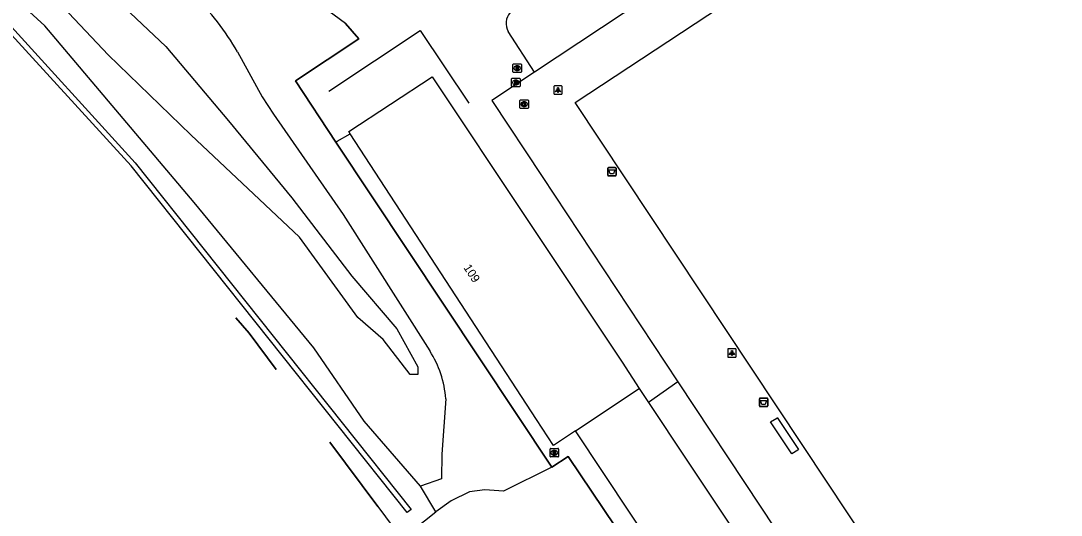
# Model space of a CAD drawing. Extents: x 155640 to 156810, y 382822 to 384046.
# Drawn here: x 156401.1 to 156523.6, y 382930.5 to 382988.7 of the extents above; entities that cross this region are included whole.
import ezdxf

# ---------------------------------------------------------------- set-up
doc = ezdxf.new("R2010")
doc.units = 0
for name, color, linetype in [('IMGEO_Afvalbak', 7, 'Continuous'), ('IMGEO_Groenvoorziening', 7, 'Continuous'), ('IMGEO_Hek', 7, 'Continuous'), ('IMGEO_Kolk', 7, 'Continuous'), ('IMGEO_Lichtpunt', 7, 'Continuous'), ('IMGEO_Pand', 7, 'Continuous'), ('IMGEO_Pand_nummerreeks', 7, 'Continuous'), ('IMGEO_Rioolput', 7, 'Continuous'), ('IMGEO_Voetpad_gesloten', 7, 'Continuous'), ('IMGEO_Voetpad_open', 7, 'Continuous')]:
    doc.layers.add(name, color=color, linetype=linetype)

msp = doc.modelspace()

# ---------------------------------------------------------------- linework, layer by layer
at = {"layer": 'IMGEO_Afvalbak'}
for p, q in [((156470.21, 382970.51), (156470.21, 382971.31)), ((156470.21, 382971.31), (156470.21, 382970.51)), ((156470.31, 382971.41), (156471.09, 382971.41)), ((156471.09, 382971.41), (156470.31, 382971.41)), ((156471.09, 382970.41), (156470.31, 382970.41)), ((156470.31, 382970.41), (156471.09, 382970.41)), ((156471.19, 382971.31), (156471.19, 382970.51)), ((156471.19, 382970.51), (156471.19, 382971.31)), ((156488.06, 382943.37), (156488.06, 382944.17)), ((156488.06, 382944.17), (156488.06, 382943.37)), ((156488.16, 382944.27), (156488.95, 382944.27)), ((156488.95, 382944.27), (156488.16, 382944.27)), ((156489.05, 382944.17), (156489.05, 382943.37)), ((156489.05, 382943.37), (156489.05, 382944.17)), ((156488.95, 382943.27), (156488.16, 382943.27)), ((156488.16, 382943.27), (156488.95, 382943.27))]:
    msp.add_line(p, q, dxfattribs=at)
for points in [[(156470.35, 382971.13), (156471.05, 382971.13), (156470.9, 382970.65), (156470.5, 382970.65), (156470.35, 382971.13)], [(156488.2, 382943.99), (156488.91, 382943.99), (156488.76, 382943.51), (156488.35, 382943.51), (156488.2, 382943.99)]]:
    msp.add_lwpolyline(points, dxfattribs=at)
for centre, start, end in [((156470.31, 382971.31), 90, 180), ((156470.31, 382971.31), 90, 180), ((156470.31, 382970.51), 180, 270), ((156470.31, 382970.51), 180, 270), ((156471.09, 382971.31), 0, 90), ((156471.09, 382971.31), 360, 90), ((156471.09, 382970.51), 270, 0), ((156471.09, 382970.51), 270, 0), ((156488.16, 382944.17), 90, 180), ((156488.16, 382944.17), 90, 180), ((156488.16, 382943.37), 180, 270), ((156488.16, 382943.37), 180, 270), ((156488.95, 382944.17), 0, 90), ((156488.95, 382944.17), 360, 90), ((156488.95, 382943.37), 270, 0), ((156488.95, 382943.37), 270, 0)]:
    msp.add_arc(centre, 0.1, start, end, dxfattribs=at)
at = {"layer": 'IMGEO_Groenvoorziening'}
for points in [[(156359.53, 383023.09), (156398.38, 382989.67), (156414.55, 382971.96), (156447.07, 382931.18), (156446.59, 382930.82), (156414.08, 382971.59), (156397.9, 382989.3), (156359.06, 383022.72), (156319.51, 383051.96), (156317.77, 383054.79), (156251.71, 383103.22), (156251.81, 383103.29), (156252.18, 383103.58), (156318.24, 383055.16), (156319.98, 383052.32), (156359.53, 383023.09)], [(156448.16, 382933.9), (156441.51, 382941.55), (156435.6, 382950.17), (156421.5, 382967.29), (156403.91, 382988.08), (156379.55, 383010.3), (156363.98, 383022.66), (156336.14, 383043.58), (156313.79, 383060.73), (156294.23, 383074.54), (156264.43, 383096.48), (156255.05, 383103.49)], [(156387.91, 383013.08), (156402.17, 383000.77), (156418.19, 382985.62), (156425.56, 382976.88), (156433.01, 382967.82), (156440.09, 382958.61), (156445.36, 382952.4), (156447.86, 382947.96), (156447.86, 382947.03)], [(156447.86, 382947.03), (156446.93, 382947.03), (156443.76, 382951.17), (156440.78, 382953.74), (156433.92, 382963.21), (156421.12, 382975.25), (156411.4, 382984.65), (156398.04, 382998.76)], [(156426.61, 382985.01), (156429.53, 382979.73), (156430.86, 382977.69), (156439.05, 382965.88), (156449.27, 382949.82)], [(156426.42, 382953.7), (156427.98, 382951.89), (156431.15, 382947.63)], [(156451.15, 382944.19), (156450.67, 382937.67), (156450.62, 382934.76), (156448.16, 382933.9)], [(156437.49, 382939.08), (156443.13, 382931.5), (156445.96, 382927.71), (156449.96, 382930.89)], [(156463.61, 382936.15), (156457.95, 382933.32), (156455.75, 382933.47), (156453.93, 382933.22), (156451.77, 382932.2), (156449.96, 382930.89)], [(156449.96, 382930.89), (156448.16, 382933.9)]]:
    msp.add_lwpolyline(points, dxfattribs=at)
for centre, radius, start, end in [((156398.25, 382968.49), 32.83, 30.2247, 45.0445), ((156438.83, 382943.19), 12.36, 4.6367, 32.4104)]:
    msp.add_arc(centre, radius, start, end, dxfattribs=at)
at = {"layer": 'IMGEO_Hek'}
for points in [[(156439.33, 382988.35), (156440.92, 382986.52), (156433.44, 382981.59), (156438.21, 382974.39)], [(156437.38, 382980.39), (156448.13, 382987.51), (156453.85, 382978.96)], [(156438.36, 382974.48), (156439.88, 382975.38)], [(156438.21, 382974.39), (156438.36, 382974.48)], [(156438.21, 382974.39), (156463.61, 382936.15), (156465.54, 382937.4), (156476.61, 382920.96)], [(156431.15, 382947.63), (156427.98, 382951.89), (156426.42, 382953.7)], [(156443.13, 382931.5), (156437.49, 382939.08)]]:
    msp.add_lwpolyline(points, dxfattribs=at)
at = {"layer": 'IMGEO_Kolk'}
for p, q in [((156459.86, 382978.43), (156459.86, 382979.28)), ((156459.94, 382979.36), (156460.79, 382979.36)), ((156460.35, 382979.13), (156460.37, 382979.13)), ((156460.86, 382979.28), (156460.86, 382978.43)), ((156460.79, 382978.35), (156459.94, 382978.35)), ((156460.37, 382978.58), (156460.35, 382978.58))]:
    msp.add_line(p, q, dxfattribs=at)
for points in [[(156459.86, 382978.43), (156459.86, 382979.28)], [(156459.94, 382979.36), (156460.79, 382979.36)], [(156460.18, 382979.05), (156460.31, 382979.05), (156460.31, 382978.9), (156460.43, 382979.05), (156460.6, 382979.05), (156460.45, 382978.9), (156460.61, 382978.65), (156460.45, 382978.65), (156460.37, 382978.82), (156460.31, 382978.75), (156460.31, 382978.65), (156460.18, 382978.65), (156460.18, 382979.05)], [(156460.86, 382979.28), (156460.86, 382978.43)], [(156460.79, 382978.35), (156459.94, 382978.35)]]:
    msp.add_lwpolyline(points, dxfattribs=at)
for centre, start, end in [((156459.94, 382979.28), 91.552, 178.448), ((156459.94, 382979.28), 91.552, 178.448), ((156460.79, 382979.28), 1.552, 88.448), ((156460.79, 382979.28), 1.552, 88.448), ((156459.94, 382978.43), 181.552, 268.448), ((156459.94, 382978.43), 181.552, 268.448), ((156460.79, 382978.43), 271.552, 358.448), ((156460.79, 382978.43), 271.552, 358.448)]:
    msp.add_arc(centre, 0.0765, start, end, dxfattribs=at)
for centre, major_axis, ratio, start_param, end_param in [((156460.35, 382978.85), (-0.387, 0.002), 0.722429, 4.712389, 7.853982), ((156460.37, 382978.85), (-0.39, 0.002), 0.717154, 1.570796, 4.712389)]:
    msp.add_ellipse(centre, major_axis=major_axis, ratio=ratio, start_param=start_param, end_param=end_param, dxfattribs=at)
at = {"layer": 'IMGEO_Lichtpunt'}
for p, q in [((156463.85, 382980.92), (156463.85, 382980.11)), ((156463.85, 382980.92), (156463.85, 382980.11)), ((156464.75, 382981.02), (156463.95, 382981.02)), ((156464.75, 382981.02), (156463.95, 382981.02)), ((156464.85, 382980.11), (156464.85, 382980.92)), ((156464.85, 382980.11), (156464.85, 382980.92)), ((156463.95, 382980.02), (156464.75, 382980.02)), ((156463.95, 382980.02), (156464.75, 382980.02)), ((156484.34, 382949.98), (156484.34, 382949.17)), ((156484.34, 382949.98), (156484.34, 382949.17)), ((156485.24, 382950.07), (156484.43, 382950.07)), ((156485.24, 382950.07), (156484.43, 382950.07)), ((156485.33, 382949.17), (156485.33, 382949.98)), ((156485.33, 382949.17), (156485.33, 382949.98)), ((156484.43, 382949.08), (156485.24, 382949.08)), ((156484.43, 382949.08), (156485.24, 382949.08))]:
    msp.add_line(p, q, dxfattribs=at)
for points in [[(156464.23, 382980.58), (156464.26, 382980.56), (156464.08, 382980.29), (156464.04, 382980.32), (156464.23, 382980.58)], [(156464.33, 382980.54), (156464.38, 382980.54), (156464.38, 382980.21), (156464.33, 382980.21), (156464.33, 382980.54)], [(156464.44, 382980.56), (156464.48, 382980.58), (156464.66, 382980.32), (156464.62, 382980.29), (156464.44, 382980.56)], [(156484.71, 382949.64), (156484.75, 382949.61), (156484.56, 382949.35), (156484.52, 382949.38), (156484.71, 382949.64)], [(156484.81, 382949.59), (156484.86, 382949.59), (156484.86, 382949.27), (156484.81, 382949.27), (156484.81, 382949.59)], [(156484.92, 382949.61), (156484.96, 382949.64), (156485.15, 382949.38), (156485.11, 382949.35), (156484.92, 382949.61)]]:
    msp.add_lwpolyline(points, dxfattribs=at)
for centre in [(156464.35, 382980.72), (156484.84, 382949.78)]:
    msp.add_circle(centre, 0.0994, dxfattribs=at)
for centre, start, end in [((156463.95, 382980.92), 90, 180), ((156463.95, 382980.92), 90, 180), ((156463.95, 382980.11), 180, 270), ((156463.95, 382980.11), 180, 270), ((156464.75, 382980.92), 0, 90), ((156464.75, 382980.92), 0, 90), ((156464.75, 382980.11), 270, 0), ((156464.75, 382980.11), 270, 360), ((156484.43, 382949.98), 90, 180), ((156484.43, 382949.98), 90, 180), ((156485.24, 382949.98), 0, 90), ((156485.24, 382949.98), 0, 90), ((156484.43, 382949.17), 180, 270), ((156484.43, 382949.17), 180, 270), ((156485.24, 382949.17), 270, 0), ((156485.24, 382949.17), 270, 360)]:
    msp.add_arc(centre, 0.0946, start, end, dxfattribs=at)
at = {"layer": 'IMGEO_Pand'}
for points in [[(156439.88, 382975.38), (156439.73, 382975.62), (156449.52, 382982.08), (156471.89, 382948.48), (156473.92, 382945.39)], [(156466.41, 382940.4), (156463.81, 382938.7), (156461.81, 382941.76), (156439.88, 382975.38)], [(156466.41, 382940.4), (156473.92, 382945.39)], [(156473.92, 382945.39), (156475, 382943.76)], [(156475, 382943.76), (156479.53, 382936.97), (156489.6, 382921.86), (156492.07, 382918.15), (156500, 382906.24), (156515.9, 382882.33), (156508.36, 382877.32)], [(156508.36, 382877.32), (156500, 382889.89), (156486.07, 382910.84), (156485.32, 382910.34), (156478.71, 382920.29), (156479.45, 382920.79), (156466.41, 382940.4)]]:
    msp.add_lwpolyline(points, dxfattribs=at)
at = {"layer": 'IMGEO_Rioolput'}
for p, q in [((156459.05, 382982.67), (156459.05, 382983.52)), ((156459.12, 382983.59), (156459.97, 382983.59)), ((156459.97, 382982.59), (156459.12, 382982.59)), ((156459.53, 382983.37), (156459.56, 382983.37)), ((156459.56, 382982.81), (156459.53, 382982.81)), ((156460.05, 382983.52), (156460.05, 382982.67)), ((156458.89, 382980.98), (156458.89, 382981.83)), ((156458.96, 382981.9), (156459.81, 382981.9)), ((156459.37, 382981.68), (156459.4, 382981.68)), ((156459.89, 382981.83), (156459.89, 382980.98)), ((156459.81, 382980.9), (156458.96, 382980.9)), ((156459.4, 382981.12), (156459.37, 382981.12)), ((156463.42, 382937.41), (156463.42, 382938.27)), ((156463.49, 382938.34), (156464.34, 382938.34)), ((156464.34, 382937.34), (156463.49, 382937.34)), ((156463.9, 382938.12), (156463.93, 382938.12)), ((156463.93, 382937.56), (156463.9, 382937.56)), ((156464.42, 382938.27), (156464.42, 382937.41))]:
    msp.add_line(p, q, dxfattribs=at)
for points in [[(156459.05, 382982.67), (156459.05, 382983.52)], [(156459.12, 382983.59), (156459.97, 382983.59)], [(156459.97, 382982.59), (156459.12, 382982.59)], [(156459.63, 382983.29), (156459.38, 382983.29), (156459.38, 382982.89)], [(156459.38, 382982.89), (156459.51, 382982.89), (156459.51, 382983.05), (156459.52, 382983.05)], [(156459.56, 382983.21), (156459.51, 382983.21), (156459.51, 382983.13)], [(156459.51, 382983.13), (156459.56, 382983.13)], [(156459.56, 382983.02), (156459.64, 382982.89), (156459.77, 382982.89), (156459.71, 382983.02)], [(156460.05, 382983.52), (156460.05, 382982.67)], [(156458.89, 382980.98), (156458.89, 382981.83)], [(156458.96, 382981.9), (156459.81, 382981.9)], [(156459.47, 382981.6), (156459.22, 382981.6), (156459.22, 382981.2)], [(156459.22, 382981.2), (156459.35, 382981.2), (156459.35, 382981.37), (156459.36, 382981.37)], [(156459.4, 382981.52), (156459.35, 382981.52), (156459.35, 382981.44)], [(156459.35, 382981.44), (156459.4, 382981.44)], [(156459.4, 382981.34), (156459.48, 382981.2), (156459.61, 382981.2), (156459.55, 382981.33)], [(156459.89, 382981.83), (156459.89, 382980.98)], [(156459.81, 382980.9), (156458.96, 382980.9)], [(156463.42, 382937.41), (156463.42, 382938.27)], [(156463.49, 382938.34), (156464.34, 382938.34)], [(156464.34, 382937.34), (156463.49, 382937.34)], [(156464, 382938.04), (156463.75, 382938.04), (156463.75, 382937.64)], [(156463.75, 382937.64), (156463.88, 382937.64), (156463.88, 382937.8), (156463.89, 382937.8)], [(156463.93, 382937.96), (156463.88, 382937.96), (156463.88, 382937.88)], [(156463.88, 382937.88), (156463.93, 382937.88)], [(156463.93, 382937.77), (156464.01, 382937.64), (156464.14, 382937.64), (156464.08, 382937.77)], [(156464.42, 382938.27), (156464.42, 382937.41)]]:
    msp.add_lwpolyline(points, dxfattribs=at)
for centre, radius, start, end in [((156459.12, 382983.52), 0.0765, 91.552, 178.448), ((156459.12, 382983.52), 0.0765, 91.552, 178.448), ((156459.12, 382982.67), 0.0765, 181.552, 268.448), ((156459.12, 382982.67), 0.0765, 181.552, 268.448), ((156459.52, 382983), 0.0533, 26.0293, 88.6989), ((156459.57, 382983.11), 0.0964, 77.0061, 93.1865), ((156459.54, 382983.32), 0.19, 274.7715, 282.9687), ((156459.58, 382983.17), 0.0378, 276.6634, 79.6772), ((156459.63, 382983.18), 0.109, 350.3612, 89.416), ((156459.63, 382983.18), 0.112, 277.5842, 350.9817), ((156459.62, 382982.96), 0.108, 29.5134, 73.7905), ((156459.97, 382983.52), 0.0765, 1.552, 88.448), ((156459.97, 382983.52), 0.0765, 1.552, 88.448), ((156459.97, 382982.67), 0.0765, 271.552, 358.448), ((156459.97, 382982.67), 0.0765, 271.552, 358.448), ((156458.96, 382981.83), 0.0765, 91.552, 178.448), ((156458.96, 382981.83), 0.0765, 91.552, 178.448), ((156459.36, 382981.31), 0.0533, 26.0293, 88.6989), ((156459.41, 382981.43), 0.0964, 77.0061, 93.1865), ((156459.38, 382981.63), 0.19, 274.7715, 282.9687), ((156459.42, 382981.48), 0.0378, 276.6634, 79.6772), ((156459.47, 382981.49), 0.109, 350.3612, 89.416), ((156459.47, 382981.49), 0.112, 277.5842, 350.9817), ((156459.46, 382981.28), 0.108, 29.5134, 73.7905), ((156459.81, 382981.83), 0.0765, 1.552, 88.448), ((156459.81, 382981.83), 0.0765, 1.552, 88.448), ((156458.96, 382980.98), 0.0765, 181.552, 268.448), ((156458.96, 382980.98), 0.0765, 181.552, 268.448), ((156459.81, 382980.98), 0.0765, 271.552, 358.448), ((156459.81, 382980.98), 0.0765, 271.552, 358.448), ((156463.49, 382938.27), 0.0765, 91.552, 178.448), ((156463.49, 382938.27), 0.0765, 91.552, 178.448), ((156463.49, 382937.42), 0.0765, 181.552, 268.448), ((156463.49, 382937.42), 0.0765, 181.552, 268.448), ((156463.89, 382937.75), 0.0533, 26.0293, 88.6989), ((156463.94, 382937.86), 0.0964, 77.0061, 93.1865), ((156463.91, 382938.07), 0.19, 274.7715, 282.9687), ((156463.95, 382937.92), 0.0378, 276.6634, 79.6772), ((156464, 382937.93), 0.109, 350.3612, 89.416), ((156464, 382937.93), 0.112, 277.5842, 350.9817), ((156463.99, 382937.71), 0.108, 29.5134, 73.7905), ((156464.34, 382938.27), 0.0765, 1.552, 88.448), ((156464.34, 382938.27), 0.0765, 1.552, 88.448), ((156464.34, 382937.42), 0.0765, 271.552, 358.448), ((156464.34, 382937.42), 0.0765, 271.552, 358.448)]:
    msp.add_arc(centre, radius, start, end, dxfattribs=at)
for centre, major_axis, ratio, start_param, end_param in [((156459.53, 382983.09), (-0.387, 0.002), 0.722429, 4.712389, 7.853982), ((156459.56, 382983.09), (-0.39, 0.002), 0.717154, 1.570796, 4.712389), ((156459.37, 382981.4), (-0.387, 0.002), 0.722429, 4.712389, 7.853982), ((156459.4, 382981.4), (-0.39, 0.002), 0.717154, 1.570796, 4.712389), ((156463.9, 382937.84), (-0.387, 0.002), 0.722429, 4.712389, 7.853982), ((156463.93, 382937.84), (-0.39, 0.002), 0.717154, 1.570796, 4.712389)]:
    msp.add_ellipse(centre, major_axis=major_axis, ratio=ratio, start_param=start_param, end_param=end_param, dxfattribs=at)
at = {"layer": 'IMGEO_Voetpad_gesloten'}
for points in [[(156438.21, 382974.39), (156438.36, 382974.48), (156439.88, 382975.38)], [(156463.61, 382936.15), (156438.21, 382974.39)], [(156502.87, 382881.43), (156484.28, 382909.39), (156483.55, 382908.9), (156475.87, 382920.48), (156476.61, 382920.96), (156465.54, 382937.4), (156463.61, 382936.15)]]:
    msp.add_lwpolyline(points, dxfattribs=at)
at = {"layer": 'IMGEO_Voetpad_open'}
for points in [[(156438.21, 382974.39), (156433.44, 382981.59), (156440.92, 382986.52), (156439.33, 382988.35), (156371.47, 383038.23), (156350.24, 383053.74)], [(156525.68, 382889.7), (156496.03, 382934.37), (156466.37, 382979.03), (156496.11, 382998.65), (156525.79, 383018.26), (156555.47, 382973.61), (156585.09, 382928.93), (156554.95, 382909.05), (156525.68, 382889.7)], [(156507.8, 383013.27), (156500, 383008.1), (156487.79, 383000), (156461.58, 382982.63)], [(156461.58, 382982.63), (156458.49, 382987.4)], [(156461.58, 382982.63), (156456.57, 382979.3), (156462.49, 382970.34), (156478.48, 382946.18)], [(156478.48, 382946.18), (156475, 382943.76)], [(156478.48, 382946.18), (156488.24, 382931.43), (156500, 382913.62), (156522.16, 382880.06)], [(156492.59, 382938.16), (156491.89, 382937.72), (156489.39, 382941.48), (156490.1, 382941.92), (156490.17, 382941.97), (156492.67, 382938.21), (156492.59, 382938.16)]]:
    msp.add_lwpolyline(points, dxfattribs=at)
msp.add_arc((156460.17, 382988.35), 1.93, 138.6147, 209.7555, dxfattribs=at)

# ---------------------------------------------------------------- texts
at = {"layer": 'IMGEO_Pand_nummerreeks'}
msp.add_text('109', height=1, rotation=303.1205, dxfattribs=at).set_placement((156453.18, 382959.62))

doc.saveas('drawing.dxf')
